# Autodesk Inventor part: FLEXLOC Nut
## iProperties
Shininess: 64.0
Length Units: 11272
Angle Units: 11279
Time Units: 11290
Mass Units: 11286
Length Display Precision: 3
Angle Display Precision: 2
Compacted: True
Part Number: FLEXLOC Nut
Document SubType Name: Modeling
Created: 2002-12
Designer: JBrentner
Description: SPS FLEXLOC NUT
Material: Steel, High Strength Low Alloy
Density: 0.0
Volumn: 0.0
Area: 0.0
PropertySet Name: Model Information
Control State: 0
Master: False
Checked Out: False
Stock: FAF_1409
DashNo: 1409
Type: FAF
Author: JBrentner
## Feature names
1. Extrusion1
2. Chamfer2
3. Chamfer3
4. Extrusion2
5. Extrusion3
6. Fillet1
7. Hole1
8. Chamfer4
9. Extrusion4
10. Circular Pattern1
